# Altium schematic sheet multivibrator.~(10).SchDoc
size 431 x 279 mm; SheetNumber: 1; SheetTotal: 1; ENG_APP_DATE: --/--/--; DSN_APP_DATE: --/--/--; CHK_APP_DATE: --/--/--
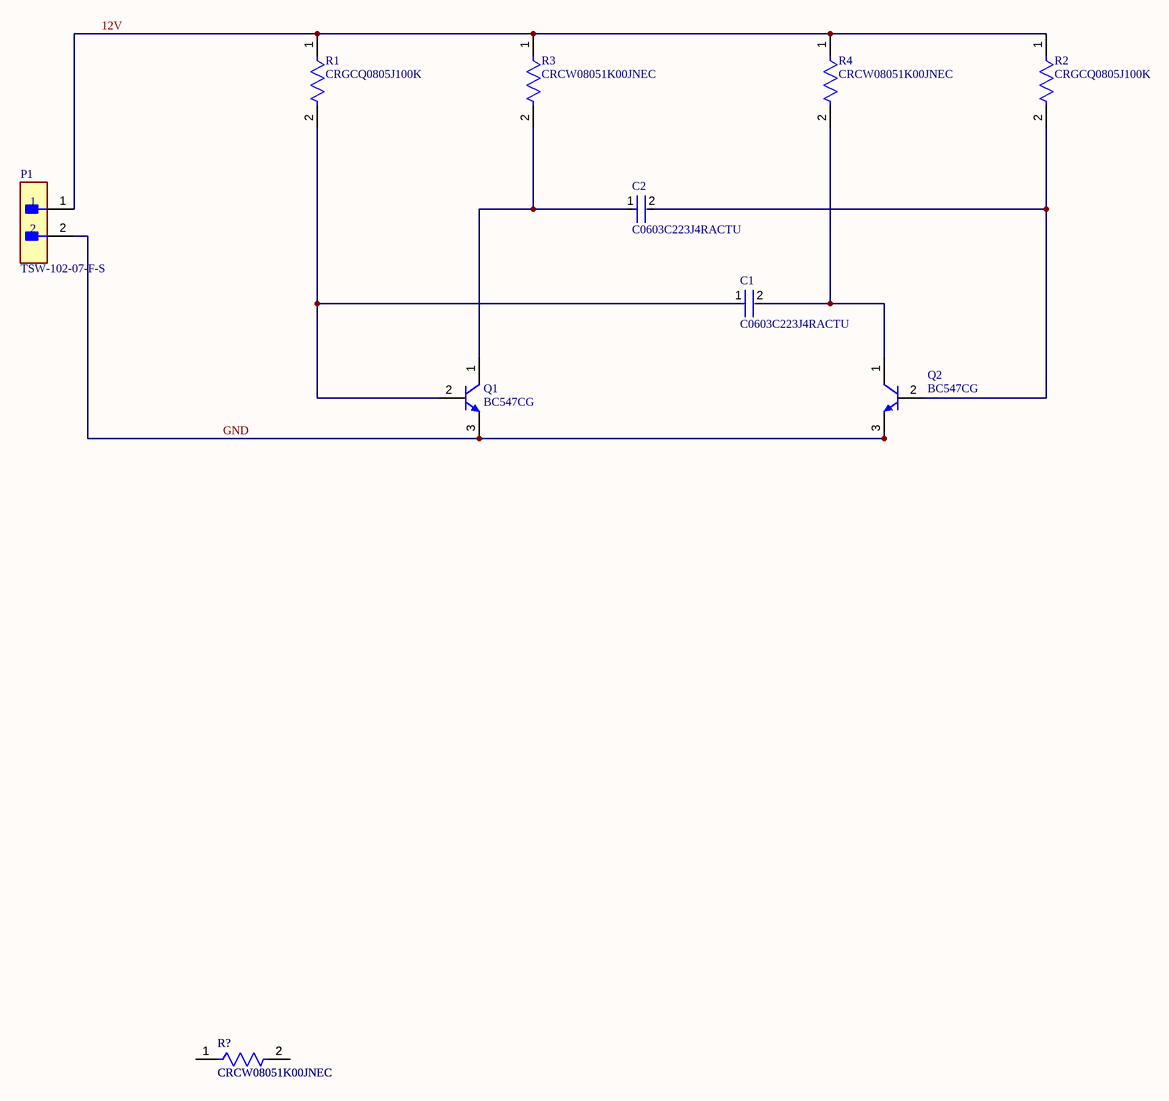
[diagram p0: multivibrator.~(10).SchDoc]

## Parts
(Parts that share a designator on the sheet are numbered #1, #2 ... from top to bottom, then left to right.)
C1  C0603C223J4RACTU  [FP-C0603C-CF-MFG]
C2  C0603C223J4RACTU  [FP-C0603C-CF-MFG]
P1  TSW-102-07-F-S  [FP-TSW-102-07-F-S-MFG]
Q1  BC547CG  [ONSC-TO-92-3-29-11]
Q2  BC547CG  [ONSC-TO-92-3-29-11]
R1  CRGCQ0805J100K  [FP-CRGCQ0805-IPC_C]
R2  CRGCQ0805J100K  [FP-CRGCQ0805-IPC_C]
R3  CRCW08051K00JNEC  [FP-CRCW0805-e3-IPC_A]
R4  CRCW08051K00JNEC  [FP-CRCW0805-e3-IPC_A]
R?#1  CRCW08051K00JNEC  [FP-CRCW0805-e3-IPC_A]
R?#2  CRCW08051K00JNEC  [FP-CRCW0805-e3-IPC_A]

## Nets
12V: P1.1 R1.1 R2.1 R3.1 R4.1
GND: P1.2 Q1.3(E) Q2.3(E)
NetC1_1: C1.1 Q1.2(B) R1.2
NetC1_2: C1.2 Q2.1(C) R4.2
NetC2_1: C2.1 Q1.1(C) R3.2
NetC2_2: C2.2 Q2.2(B) R2.2
NetR?#1_1: R?#1.1 R?#2.1
NetR?#1_2: R?#1.2 R?#2.2

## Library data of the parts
C1 C2 = CMP-2006-03745-2: CAP CER 0.022UF 16V 5% X7R 0603; Manufacturer: KEMET; Tolerance: 0.05; Automotive Grade: Grade 1; Temperature Coefficient: 30ppm/°C; Capacitance: 22,000 pF; Material: Ceramic; Value: 22,000 pF
P1 = CMP-02766-001458-1: CONN HEADER VERT 2POS 2.54MM; Gender: Male; Max Current Rating: 7.6A; Number of Contacts: 2; Max Voltage Rating (AC): 550V
Q1 Q2 = CMP-1048-01464-1: Amplifier Transistor, NPN Silicon, 3-Pin TO-92, Pb-Free, Bulk Box; Manufacturer: On Semiconductor; IC Continuous (A): 0.1; fT Min (MHz): 150
R1 R2 = CMP-03211-009742-1: CRGCQ0805 100KΩ 0.125W ±100ppm/°C 5% 150V; Manufacturer: TE Connectivity; Tolerance: 0.05
R3 R4 R?#1 R?#2 = CMP-02407-005778-1: RES Thick Film, 1kΩ, 5%, 0.125W, 200ppm/°C, 0805; Max Power Dissipation: 125mW; Resistance: 1kR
